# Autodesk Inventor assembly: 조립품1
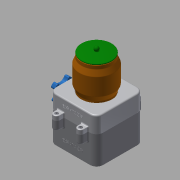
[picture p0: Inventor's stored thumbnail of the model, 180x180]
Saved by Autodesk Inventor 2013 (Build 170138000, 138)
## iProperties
Created: 2018-01
Part Number: 조립품1
Document SubType Name: Assembly
Designer: Administrator
Author: Administrator
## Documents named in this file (9)
- C:\Users\Administrator\Desktop\480108V1026\조립품1.iam
- C:\Users\Administrator\Desktop\480108V1026\본체.ipt
- C:\Users\Administrator\Desktop\480108V1026\본체커버.ipt
- C:\Users\Administrator\Desktop\480108V1026\핸들축.ipt
- C:\Users\Administrator\Desktop\480108V1026\핸들.ipt
- C:\Users\Administrator\Desktop\480108V1026\볼트 M3x12.ipt
- C:\Users\Administrator\Desktop\480108V1026\용기.ipt
- C:\Users\Administrator\Desktop\480108V1026\용기캡.ipt
- C:\Users\Administrator\Desktop\480108V1026\볼트 M4x12.ipt
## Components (2 placed, 2 different names)
1. 핸들축:1
2. 핸들:1 — 플러쉬:1
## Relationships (1: Flush 1)
- 플러쉬:1 [Flush]: 핸들:1
